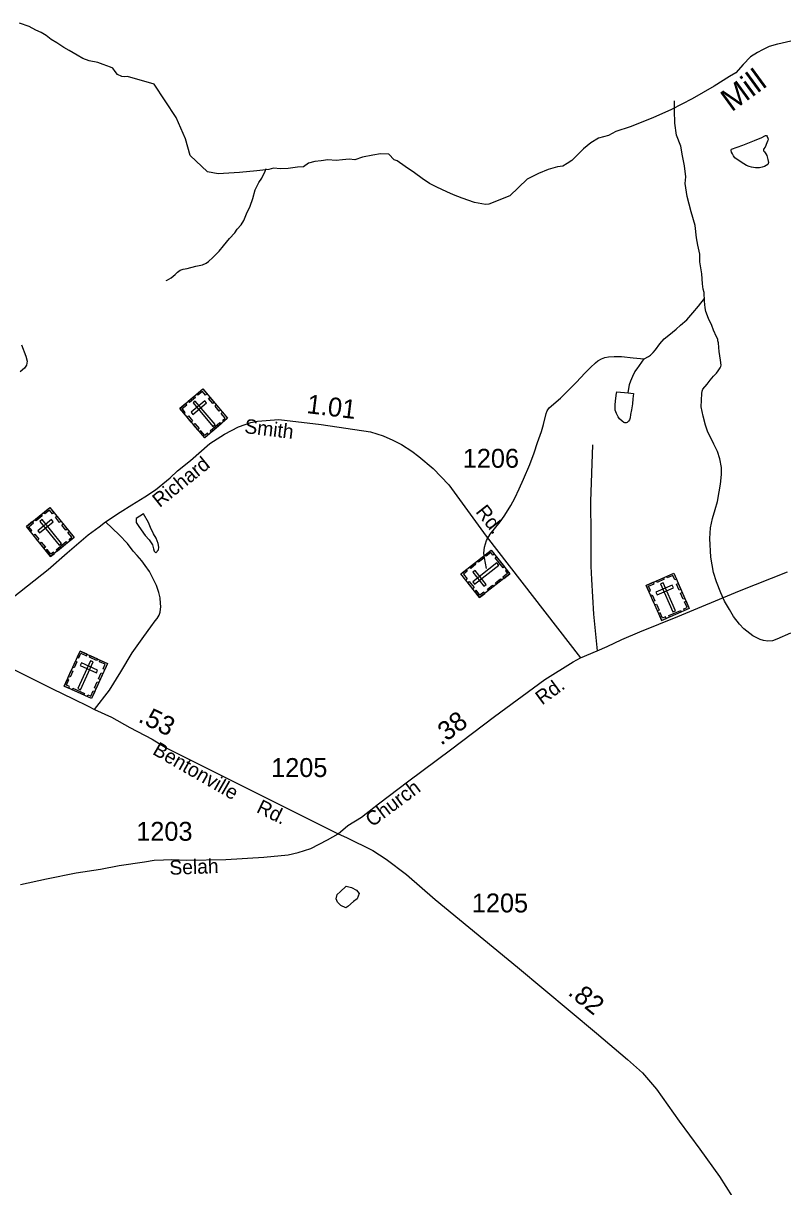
# Model space of a CAD drawing. Extents: x 2206922 to 2357709, y 510027 to 673830.
# Drawn here: x 2222859 to 2227881, y 565687 to 573378 of the extents above; entities that cross this region are included whole.
import ezdxf

# ---------------------------------------------------------------- set-up
doc = ezdxf.new("R2010")
doc.units = 0
for name, color, linetype in [('Exist Boundary Political CountyLine', 7, 'Continuous'), ('Exist Cultural Cemetery CELL', 7, 'Continuous'), ('Exist Hydrographic Creek Single Shore Label', 7, 'Continuous'), ('Exist Hydrographic Misc Water Feature', 7, 'Continuous'), ('Exist Road Non-System Type 51', 7, 'Continuous'), ('Exist Road Secondary Mileage Hundredths English Label', 7, 'Continuous'), ('Exist Road Secondary Type 51 Attributed', 7, 'Continuous'), ('Exist Road Secondary Type 51 Label', 7, 'Continuous'), ('Exist Road Secondary Type 51 Number Label', 7, 'Continuous')]:
    doc.layers.add(name, color=color, linetype=linetype)

msp = doc.modelspace()

# ---------------------------------------------------------------- linework, layer by layer
at = {"layer": 'Exist Boundary Political CountyLine'}
for points in [[(2225169.4, 572505.8), (2225101.8, 572493.3), (2225050.7, 572475.9), (2225014.8, 572478.9), (2224969.5, 572475.9), (2224927.1, 572471.6), (2224872.5, 572475.9), (2224829, 572467.7), (2224787.8, 572463.4), (2224744.6, 572453.6), (2224712.2, 572428.1), (2224672.2, 572426.7), (2224610.5, 572418.6), (2224560, 572416.4), (2224513.1, 572419), (2224482.1, 572411.5), (2224402.9, 572402.6), (2224288.5, 572391.1), (2224147.7, 572382.9), (2224077.5, 572395.6), (2223962.9, 572503.2), (2223931.3, 572613.5), (2223871, 572754), (2223724.8, 572975.1), (2223547.7, 573026.8), (2223530.5, 573023.2), (2223510.6, 573026.6), (2223482.5, 573039.1), (2223467.7, 573058), (2223450.3, 573081.5), (2223435.3, 573088.6), (2223386.5, 573106.2), (2223351.2, 573119.4), (2223294.8, 573129.4), (2223253.4, 573145), (2223216.5, 573167), (2223163.4, 573198.5), (2223126.7, 573218.6), (2223080.8, 573248.2), (2223044.7, 573270.6), (2223010.2, 573296.2), (2222977.4, 573317.8), (2222941.3, 573331.4), (2222898.1, 573355.4), (2222834.7, 573377.8)], [(2227933.9, 573258.6), (2227849.1, 573240.6), (2227847, 573240.2), (2227791.2, 573223.4), (2227746.5, 573201.4), (2227713.9, 573184.5), (2227668, 573157), (2227618.6, 573104.2), (2227570, 573051), (2227527.7, 573026.6), (2227427.3, 572962.2), (2227282.1, 572878.2), (2227145.7, 572808.2), (2227021.3, 572753.4), (2226871.2, 572693.4), (2226777.7, 572662.5), (2226728, 572637), (2226663.6, 572617.7), (2226611.2, 572587.7), (2226564.4, 572548.6), (2226531.8, 572517.8), (2226486.5, 572471.7), (2226455.3, 572451.7), (2226427.2, 572433.8), (2226392, 572429.8), (2226329.2, 572411), (2226265.2, 572385), (2226190.8, 572347), (2226132.8, 572291.8), (2226077.2, 572237.4), (2225936.5, 572181.3), (2225915.8, 572179.7), (2225842.8, 572192.5), (2225760.2, 572222.5), (2225704.8, 572244.8), (2225660.5, 572263.8), (2225594.5, 572294.6), (2225545.9, 572319.4), (2225496.7, 572352.6), (2225446.5, 572388.5), (2225383.3, 572430.2), (2225330.4, 572467.4), (2225312.6, 572475.4), (2225276.5, 572512.9), (2225220.3, 572514.4), (2225169.4, 572505.8)]]:
    msp.add_lwpolyline(points, dxfattribs=at)
at = {"layer": 'Exist Cultural Cemetery CELL'}
for points in [[(2223893.9, 570831.4), (2224045.4, 570960.6), (2224210.5, 570766.8), (2224059, 570637.6)], [(2223950.2, 570879.4), (2223989.7, 570913.1), (2223997.1, 570904.4), (2223957.6, 570870.8)], [(2224073.5, 570927.6), (2224064.9, 570920.2), (2224044, 570944.7), (2224013.2, 570918.4), (2224005.9, 570926.9), (2224045.4, 570960.6)], [(2224112.3, 570864.6), (2224084.2, 570897.6), (2224092.8, 570904.9), (2224120.9, 570872)], [(2223921.9, 570798.4), (2223930.6, 570805.8), (2223909.7, 570830.3), (2223940.6, 570856.6), (2223933.3, 570865.1), (2223893.9, 570831.4)], [(2223969.1, 570806.1), (2223981.2, 570791.9), (2224070.8, 570868.3), (2224058.7, 570882.5)], [(2223995.8, 570879.8), (2223981.6, 570867.7), (2224113.2, 570713.4), (2224127.4, 570725.5)], [(2224155, 570814.4), (2224126.9, 570847.4), (2224135.6, 570854.8), (2224163.7, 570821.8)], [(2223970, 570742), (2223941.9, 570775), (2223950.6, 570782.3), (2223978.7, 570749.4)], [(2224095.3, 570683.6), (2224159.9, 570738.7), (2224167.3, 570730), (2224102.7, 570675)], [(2224185.3, 570745.3), (2224177.9, 570754), (2224194.6, 570768.3), (2224168.4, 570799.1), (2224176.9, 570806.3), (2224210.5, 570766.8)], [(2224013.6, 570690.8), (2223985.5, 570723.8), (2223994.2, 570731.2), (2224022.3, 570698.2)], [(2224084.2, 570659.1), (2224076.7, 570667.9), (2224060, 570653.6), (2224033.8, 570684.4), (2224025.3, 570677.1), (2224059, 570637.6)], [(2222880.1, 570050.7), (2223034.8, 570175.9), (2223195, 569978), (2223040.3, 569852.8)], [(2222937.7, 570097.3), (2222977.9, 570129.9), (2222985.1, 570121), (2222944.8, 570088.4)], [(2223062.2, 570142.3), (2223053.3, 570135.1), (2223033.1, 570160.2), (2223001.6, 570134.6), (2222994.6, 570143.3), (2223034.9, 570175.9)], [(2222907.3, 570017), (2222916.2, 570024.1), (2222895.9, 570049.2), (2222927.4, 570074.7), (2222920.4, 570083.3), (2222880.1, 570050.7)], [(2222954.6, 570023.5), (2222966.4, 570008.9), (2223057.9, 570083), (2223046.1, 570097.5)], [(2222983.3, 570096.5), (2222968.7, 570084.7), (2223096.3, 569927.1), (2223110.9, 569938.9)], [(2223099.3, 570078.3), (2223072, 570112), (2223080.9, 570119.1), (2223108.1, 570085.5)], [(2223140.7, 570027), (2223113.5, 570060.7), (2223122.3, 570067.9), (2223149.6, 570034.2)], [(2222954, 569959.4), (2222926.7, 569993), (2222935.6, 570000.2), (2222962.8, 569966.5)], [(2223169.3, 569957.2), (2223162.1, 569966.1), (2223179.2, 569980), (2223153.7, 570011.4), (2223162.4, 570018.4), (2223195, 569978)], [(2222996.3, 569907.1), (2222969, 569940.8), (2222977.9, 569947.9), (2223005.1, 569914.3)], [(2223066, 569873.6), (2223058.8, 569882.5), (2223041.7, 569868.7), (2223016.2, 569900.1), (2223007.6, 569893.1), (2223040.2, 569852.8)], [(2223077.7, 569897.8), (2223143.7, 569951.2), (2223150.9, 569942.4), (2223084.9, 569889)], [(2225876.7, 569581.8), (2225753.4, 569738.1), (2225953.3, 569895.8), (2226076.6, 569739.5)], [(2225973.8, 569869.8), (2225964.8, 569862.6), (2225951.2, 569879.9), (2225919.4, 569854.9), (2225912.6, 569863.6), (2225953.3, 569895.8)], [(2225903.6, 569842.1), (2225869.6, 569815.3), (2225862.5, 569824.2), (2225896.5, 569851)], [(2226032, 569777.5), (2225979.4, 569844.1), (2225988.4, 569851.1), (2226041, 569784.5)], [(2225787.4, 569765), (2225794.4, 569756.1), (2225769.1, 569736.1), (2225794.3, 569704.3), (2225785.5, 569697.4), (2225753.4, 569738.1)], [(2225851.8, 569801.3), (2225817.8, 569774.4), (2225810.8, 569783.4), (2225844.8, 569810.2)], [(2225904.8, 569655.9), (2225919.5, 569667.5), (2225846.6, 569760), (2225831.9, 569748.4)], [(2225832.2, 569685.5), (2225843.7, 569670.8), (2226002.9, 569796.4), (2225991.4, 569811.1)], [(2226056.1, 569765.4), (2226047.1, 569758.3), (2226060.7, 569741), (2226029, 569716), (2226035.8, 569707.2), (2226076.6, 569739.4)], [(2226977.9, 569662.4), (2227160.1, 569742.5), (2227262.6, 569509.3), (2227080.3, 569429.3)], [(2227177.7, 569702.8), (2227167.3, 569698.2), (2227154.3, 569727.7), (2227117.2, 569711.4), (2227112.7, 569721.6), (2227160.2, 569742.4)], [(2225830.8, 569639.9), (2225798.7, 569680.6), (2225807.7, 569687.7), (2225839.8, 569647)], [(2225968.9, 569654.5), (2225934.9, 569627.7), (2225927.9, 569636.6), (2225961.9, 569663.4)], [(2226021.7, 569696.1), (2225987.7, 569669.3), (2225980.7, 569678.2), (2226014.7, 569705.1)], [(2226995.3, 569622.7), (2227005.7, 569627.3), (2226992.7, 569656.8), (2227029.9, 569673.1), (2227025.4, 569683.3), (2226977.9, 569662.4)], [(2227042.6, 569616.5), (2227050.1, 569599.4), (2227157.9, 569646.8), (2227150.4, 569663.9)], [(2227045.7, 569692.2), (2227093.1, 569713), (2227097.7, 569702.6), (2227050.3, 569681.7)], [(2227089.5, 569679.4), (2227072.4, 569671.9), (2227153.9, 569486.2), (2227171, 569493.8)], [(2227196.6, 569631.3), (2227179.2, 569671), (2227189.6, 569675.5), (2227207, 569635.9)], [(2225910.7, 569608.6), (2225903.7, 569617.5), (2225878.4, 569597.6), (2225853.3, 569629.4), (2225844.5, 569622.5), (2225876.7, 569581.8)], [(2227025.1, 569554.8), (2227007.7, 569594.5), (2227018.1, 569599.1), (2227035.5, 569559.4)], [(2227223.1, 569570.9), (2227205.7, 569610.6), (2227216.1, 569615.2), (2227233.5, 569575.5)], [(2227052.1, 569493.3), (2227034.7, 569532.9), (2227045.1, 569537.5), (2227062.6, 569497.9)], [(2227232.2, 569496), (2227227.6, 569506.5), (2227247.8, 569515.4), (2227231.5, 569552.4), (2227241.7, 569556.9), (2227262.6, 569509.3)], [(2227110.6, 569442.6), (2227105.9, 569453.1), (2227085.8, 569444.3), (2227069.5, 569481.3), (2227059.4, 569476.8), (2227080.2, 569429.3)], [(2227128.3, 569462.9), (2227206, 569497), (2227210.6, 569486.6), (2227132.9, 569452.4)], [(2223234.3, 569228.3), (2223415.7, 569146.3), (2223310.8, 568914.3), (2223129.4, 568996.3)], [(2223216.5, 569188.9), (2223226.8, 569184.2), (2223240.1, 569213.5), (2223277, 569196.8), (2223281.6, 569206.9), (2223234.3, 569228.3)], [(2223301.8, 569197.8), (2223349, 569176.4), (2223344.3, 569166), (2223297.1, 569187.4)], [(2223185.9, 569121.3), (2223203.8, 569160.8), (2223214.1, 569156.1), (2223196.3, 569116.6)], [(2223321.6, 569156.7), (2223304.6, 569164.4), (2223221, 568979.6), (2223238, 568971.9)], [(2223243.5, 569149.5), (2223235.8, 569132.5), (2223343, 569083.9), (2223350.7, 569101)], [(2223397.9, 569106.7), (2223387.6, 569111.4), (2223400.8, 569140.7), (2223363.9, 569157.4), (2223368.5, 569167.6), (2223415.8, 569146.2)], [(2223159.5, 568982.8), (2223164.3, 568993.2), (2223144.2, 569002.3), (2223160.9, 569039.1), (2223150.7, 569043.7), (2223129.3, 568996.4)], [(2223158.2, 569060.1), (2223176, 569099.5), (2223186.4, 569094.8), (2223168.5, 569055.4)], [(2223357.4, 569044.8), (2223375.2, 569084.3), (2223385.6, 569079.6), (2223367.8, 569040.2)], [(2223186.5, 568983.1), (2223263.8, 568948.1), (2223259.1, 568937.7), (2223181.8, 568972.7)], [(2223330.2, 568984.8), (2223348, 569024.3), (2223358.4, 569019.6), (2223340.6, 568980.1)], [(2223280.6, 568927.9), (2223285.3, 568938.4), (2223305.3, 568929.3), (2223322, 568966.1), (2223332.1, 568961.6), (2223310.8, 568914.3)]]:
    msp.add_lwpolyline(points, close=True, dxfattribs=at)
at = {"layer": 'Exist Hydrographic Misc Water Feature'}
msp.add_line((2223805.2, 571676), (2223806, 571676.6), dxfattribs=at)
for points in [[(2227364.1, 571559.2), (2227362.3, 571580.9), (2227360.2, 571599.1), (2227355.7, 571620.8), (2227349.5, 571654.6), (2227345.2, 571720.6), (2227340.9, 571748.8), (2227332.1, 571800.8), (2227331.9, 571850.7), (2227319.4, 571910.6), (2227310.8, 571958.5), (2227300.7, 572040.4), (2227275.5, 572132.1), (2227249.3, 572231.8), (2227236.4, 572317.7), (2227239.8, 572361.8), (2227231.2, 572435.6), (2227218.9, 572501.2), (2227206.2, 572565.1), (2227177.5, 572638.8), (2227167.3, 572716.6), (2227164.2, 572800.6), (2227165.5, 572865.9)], [(2227761.7, 572633.8), (2227767, 572635.8), (2227773.4, 572635.7), (2227777.5, 572629.8), (2227781.6, 572617.8), (2227783.4, 572611.9), (2227781.6, 572603.6), (2227780, 572597.8), (2227775.6, 572587.9), (2227763.8, 572559.7), (2227754.1, 572545.7), (2227754.3, 572541.7), (2227754.1, 572535.6), (2227760.1, 572527.8), (2227768.3, 572515.6), (2227776.5, 572503.8), (2227782.8, 572477.7), (2227786.7, 572458.1), (2227785.1, 572449.8), (2227783.2, 572444.1), (2227771.1, 572437.7), (2227761.1, 572432), (2227745.3, 572425.8), (2227727.3, 572421.7), (2227701, 572423.2), (2227675, 572427.1), (2227659, 572430.7), (2227641.1, 572438.7), (2227604.8, 572460.4), (2227564.9, 572488.3), (2227554.8, 572502), (2227548.7, 572513.9), (2227542.1, 572525.8), (2227540.5, 572535.8), (2227540.2, 572541.9), (2227542.1, 572546.1), (2227616.3, 572572.6), (2227693.6, 572603.1), (2227741.6, 572623.5), (2227761.7, 572633.8)], [(2223806, 571676.6), (2223836.6, 571694.4), (2223862.8, 571716.4), (2223878.4, 571732.7), (2223896.5, 571746.6), (2223916.6, 571752.9), (2223942.4, 571757.1), (2224000.4, 571771.4), (2224044.3, 571781.8), (2224068.1, 571792), (2224083.7, 571803.9), (2224111.8, 571830.5), (2224155, 571870.6), (2224182.7, 571906.9), (2224222.3, 571955.3), (2224258.2, 571991.7), (2224274, 572017.7), (2224299.8, 572045.8), (2224317.2, 572074), (2224335.3, 572117.9), (2224358.9, 572168.3), (2224376.1, 572220.4), (2224391.9, 572276.5), (2224417.7, 572324.5), (2224435.6, 572354.7), (2224458.9, 572401), (2224464.9, 572418.7)], [(2226964, 571159.7), (2226993.6, 571174.2), (2227005.5, 571184.2), (2227023.5, 571200.6), (2227039.3, 571218.5), (2227067.2, 571258.4), (2227096.7, 571290.9), (2227126.9, 571315.1), (2227176.1, 571355.6), (2227205.8, 571381.9), (2227247.6, 571418.2), (2227287.2, 571464.5), (2227323.1, 571508.6), (2227364.1, 571559.2)], [(2227932.1, 569346.5), (2227840.9, 569305.9), (2227812.8, 569295.6), (2227782.6, 569293.2), (2227752.7, 569297.3), (2227730.5, 569305.1), (2227704.5, 569316.8), (2227682.1, 569328.6), (2227662.3, 569344.2), (2227624.1, 569375.9), (2227594, 569406), (2227555.4, 569455.6), (2227529.4, 569503.4), (2227496.6, 569557), (2227472.4, 569612.5), (2227443.5, 569684.6), (2227423, 569748.1), (2227404.5, 569848.2), (2227399.6, 569971.8), (2227402.7, 570041.9), (2227416.4, 570103.9), (2227433.6, 570164.2), (2227449.6, 570216.1), (2227461.1, 570280.5), (2227470.3, 570330.6), (2227475.9, 570394.3), (2227475.2, 570442.2), (2227465, 570498.1), (2227448.4, 570546), (2227426, 570596), (2227403.9, 570641.5), (2227385.8, 570675.5), (2227369.2, 570721.4), (2227354.9, 570781.1), (2227342.4, 570843.1), (2227343.6, 570887), (2227345.4, 570931), (2227347.5, 570945.3), (2227353, 570959), (2227380.9, 570991.3), (2227401, 571019.5), (2227422.3, 571045.5), (2227442.2, 571065.6), (2227454.3, 571080), (2227468.1, 571100.2), (2227471.8, 571108.1), (2227474, 571118), (2227469.5, 571149.9), (2227461.3, 571207.9), (2227459.3, 571233.8), (2227456.8, 571265.7), (2227452.5, 571277.8), (2227450.6, 571289.8), (2227442.2, 571305.7), (2227424, 571349.4), (2227412.1, 571379.6), (2227389.5, 571425.2), (2227373.1, 571473), (2227368.8, 571497.2), (2227364.5, 571540.9), (2227364.1, 571559.2)], [(2225921.4, 569773.9), (2225909.3, 569843.9), (2225904.8, 569875.8), (2225908.4, 569913.8), (2225921.8, 569958), (2225946, 570000.2), (2226013.2, 570082.5), (2226038.6, 570118.8), (2226054.6, 570142.8), (2226081.9, 570189.3), (2226109.8, 570239.4), (2226137.3, 570299.4), (2226166.6, 570363.9), (2226207.6, 570461.9), (2226237.3, 570538.1), (2226258.5, 570606.3), (2226286.4, 570678.8), (2226299.3, 570726.6), (2226316.9, 570798.6), (2226322.9, 570816.8), (2226337, 570835), (2226412.3, 570899.4), (2226471.7, 570958.1), (2226517.2, 571006.4), (2226572.8, 571064.6), (2226610.7, 571103.1), (2226642.5, 571133.2), (2226658.1, 571147.4), (2226682.1, 571159.6), (2226703.8, 571167.7), (2226728, 571172.1), (2226765.8, 571174.2), (2226815.6, 571174.7), (2226891.7, 571167.3), (2226964, 571159.7)], [(2226857.8, 570935.2), (2226867.3, 570989.3), (2226877.1, 571015), (2226888.8, 571045.3), (2226902.5, 571073.6), (2226918.1, 571093.6), (2226964, 571159.7)], [(2226857.8, 570935.2), (2226893.7, 570931.4), (2226889.8, 570895.5), (2226888.4, 570861.3), (2226880.8, 570823.4), (2226875.1, 570791.5), (2226871.4, 570769.3), (2226866.9, 570755.4), (2226861.3, 570747.3), (2226853.1, 570739.2), (2226845.1, 570737.2), (2226837.5, 570737.1), (2226829.3, 570739.1), (2226819.1, 570746.8), (2226801, 570762.9), (2226793, 570776.7), (2226780.5, 570798.4), (2226776.8, 570808.7), (2226772.3, 570820.4), (2226772.1, 570852.4), (2226775.8, 570882.7), (2226781.6, 570932.5), (2226783.8, 570940.7), (2226857.8, 570935.2)], [(2223653.3, 570136), (2223605.3, 570103.5), (2223605.3, 570077.6), (2223617.8, 570057.9), (2223639.7, 570029.8), (2223664.1, 569992), (2223691.8, 569962.3), (2223714.2, 569930.6), (2223720.5, 569904.5), (2223724.2, 569888.5), (2223736.7, 569876.9), (2223752.3, 569896.8), (2223754.6, 569914.7), (2223750.5, 569938.9), (2223738.2, 569974.8), (2223719.9, 570002.7), (2223699.6, 570044.3), (2223687.3, 570078.2), (2223653.3, 570136)], [(2224995.1, 567673.6), (2225029.2, 567665.6), (2225061.6, 567648.1), (2225079.6, 567624.4), (2225067.5, 567590.1), (2225042.1, 567572), (2225006, 567539.7), (2224992.1, 567529.7), (2224958.2, 567545.4), (2224937.9, 567567), (2224927.9, 567590.9), (2224935.5, 567618.9), (2224953.5, 567637.3), (2224995.1, 567673.6)]]:
    msp.add_lwpolyline(points, dxfattribs=at)
at = {"layer": 'Exist Road Non-System Type 51'}
for points in [[(2222847, 571252.4), (2222876.3, 571177.1), (2222884, 571145.2), (2222882.7, 571129.9), (2222881.4, 571117.1), (2222867.4, 571098), (2222838.2, 571073)], [(2226622.6, 570591.6), (2226609.6, 570217.6), (2226611.6, 569995.8), (2226611.2, 569789.9), (2226615.8, 569702), (2226629.8, 569472.2), (2226653.8, 569228.4)], [(2223329.4, 568840.7), (2223428.3, 568970.3), (2223503.7, 569090.5), (2223579.1, 569215.4), (2223655.6, 569323.8), (2223701.6, 569387.4), (2223732.2, 569427.5), (2223745.2, 569442.2), (2223757, 569464.1), (2223764.1, 569484.9), (2223767.8, 569522.9), (2223767.6, 569542.9), (2223765.4, 569578.9), (2223755.1, 569614.7), (2223740.8, 569660.8), (2223720.6, 569700.6), (2223692.8, 569754.5), (2223664.1, 569792.7), (2223643, 569823.4), (2223612.4, 569859.7), (2223585.6, 569888.4), (2223547.4, 569938.2), (2223493.8, 569995.6), (2223403.9, 570081.8)]]:
    msp.add_lwpolyline(points, dxfattribs=at)
at = {"layer": 'Exist Road Secondary Type 51 Attributed'}
for points in [[(2222684, 569500.6), (2222887.4, 569658.7), (2223023.2, 569767.9), (2223149.5, 569877), (2223289.1, 569995.6), (2223361.8, 570049.2), (2223403.9, 570081.8), (2223500.5, 570146.8), (2223576.1, 570194.7), (2223662.2, 570246.4), (2223732.9, 570294.2), (2223829.7, 570373.2), (2223880, 570420), (2223964.4, 570486.5), (2224091.9, 570599.7), (2224190.7, 570662.6), (2224282.3, 570711.1), (2224363.1, 570738.1), (2224408, 570747), (2224549.9, 570757.8), (2224828.5, 570724.8), (2225155.2, 570677), (2225239.6, 570650), (2225302.5, 570623), (2225359.9, 570594.3), (2225428.2, 570549.4), (2225474.9, 570513.4), (2225568.3, 570434.4), (2225672.4, 570326.5), (2225920.3, 569986.9), (2226544.2, 569183.6)], [(2226544.2, 569183.6), (2226653.8, 569228.4), (2226719.4, 569259), (2226816.5, 569304), (2226935, 569354.3), (2227187.7, 569456.7), (2227594, 569625.8), (2227912.1, 569751.5)], [(2222417.9, 569286.1), (2222554.5, 569218.5), (2222645.4, 569172.6), (2222753.5, 569128.5), (2222921.3, 569043.3), (2223051.8, 568978.2), (2223188.2, 568913.1), (2223288.4, 568863.9), (2223329.4, 568840.7), (2223442.9, 568791), (2223562.9, 568722.4), (2223710.5, 568645.6), (2223804.5, 568588.1), (2224941.4, 568020.3)], [(2224941.4, 568020.3), (2225005.8, 568075.7), (2225095.5, 568130.2), (2225208.6, 568217.1), (2225409.3, 568370.8), (2225683.6, 568574.8), (2225975.7, 568795.2), (2226307.5, 569039.8), (2226495, 569156.6), (2226544.2, 569183.6)], [(2222841.8, 567685.9), (2223013.8, 567721.2), (2223209.3, 567761.3), (2223369.5, 567787.2), (2223494.3, 567810.8), (2223661.4, 567834.8), (2223725.3, 567845.3), (2223785.3, 567847.6), (2223840.9, 567849.5), (2223940.6, 567845.7), (2224197.5, 567849.5), (2224450.6, 567864.9), (2224609.7, 567880.2), (2224676.8, 567895.6), (2224761.2, 567923.4), (2224870.8, 567980.6), (2224941.4, 568020.3)], [(2224941.4, 568020.3), (2224996.6, 567995.7), (2225169.5, 567910), (2225257.7, 567852.4), (2225393.9, 567750.8), (2225583.7, 567586.7), (2226127, 567139.3), (2226649.7, 566701.4), (2226854.8, 566528.8), (2226952.4, 566440.2), (2227045.2, 566332.9), (2227196.1, 566120.2), (2227332.3, 565935.5), (2227461.6, 565754.7), (2227589.3, 565555.8), (2227642, 565458.3), (2227672.8, 565360.5), (2227687.4, 565284.7), (2227695.9, 565220.9), (2227718.9, 565099.1), (2227750.3, 564923.5)]]:
    msp.add_lwpolyline(points, dxfattribs=at)

# ---------------------------------------------------------------- texts
at = {"layer": 'Exist Hydrographic Creek Single Shore Label'}
msp.add_text('Mill', height=150, rotation=36.12846, dxfattribs=at).set_placement((2227542.1, 572788.2))
at = {"layer": 'Exist Road Secondary Mileage Hundredths English Label'}
for s, rotation, p in [('1.01', 352.93127, (2224728.9, 570801.4)), ('.53', 333.86499, (2223612.9, 568763.7)), ('.38', 37.02665, (2225622, 568600.2)), ('.82', 321.06501, (2226454.2, 566960.6))]:
    msp.add_text(s, height=125, rotation=rotation, dxfattribs=at).set_placement(p)
at = {"layer": 'Exist Road Secondary Type 51 Label'}
for s, rotation, p in [('Smith', 352.93128, (2224318, 570669.4)), ('Richard', 38.86604, (2223760.7, 570172.9)), ('Rd.', 308.27041, (2225846.2, 570147.8)), ('Rd.', 36.39745, (2226289.6, 568867.5)), ('Bentonville', 330.06722, (2223707.9, 568549.8)), ('Church', 36.64824, (2225166.2, 568061.4)), ('Rd.', 333.86499, (2224394.5, 568165.4)), ('Selah', 2.08302, (2223827.2, 567748.6))]:
    msp.add_text(s, height=95, rotation=rotation, dxfattribs=at).set_placement(p)
at = {"layer": 'Exist Road Secondary Type 51 Number Label'}
for s, p in [('1206', (2225765.1, 570439.6)), ('1205', (2224498.1, 568395.4)), ('1203', (2223606.3, 567973.8)), ('1205', (2225825.2, 567500.3))]:
    msp.add_text(s, height=125, dxfattribs=at).set_placement(p)

doc.saveas('drawing.dxf')
